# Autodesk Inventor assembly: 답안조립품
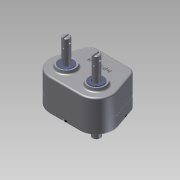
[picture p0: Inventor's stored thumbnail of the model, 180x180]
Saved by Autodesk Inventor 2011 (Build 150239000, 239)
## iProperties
Created: 2014-12
Part Number: 답안조립품
Document SubType Name: Assembly
Designer: SDA
Author: SDA
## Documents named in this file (17)
- C:\Users\SDA\Desktop\441208V1026\답안조립품.iam
- C:\Users\SDA\Desktop\441208V1026\M 5 x 35.ipt
- C:\Users\SDA\Desktop\441208V1026\멈춤링.ipt
- C:\Users\SDA\Desktop\441208V1026\메인기어.ipt
- C:\Users\SDA\Desktop\441208V1026\메인축.ipt
- C:\Users\SDA\Desktop\441208V1026\베어링- 6202.ipt
- C:\Users\SDA\Desktop\441208V1026\베어링- 6203.ipt
- C:\Users\SDA\Desktop\441208V1026\본체.ipt
- C:\Users\SDA\Desktop\441208V1026\서브기어.ipt
- C:\Users\SDA\Desktop\441208V1026\서브축.ipt
- C:\Users\SDA\Desktop\441208V1026\오일시일-D-15.ipt
- C:\Users\SDA\Desktop\441208V1026\오일시일-D-17.ipt
- C:\Users\SDA\Desktop\441208V1026\커버.ipt
- C:\Users\SDA\Desktop\441208V1026\키5x5.ipt
- C:\Users\SDA\Desktop\441208V1026\서브기어_CPY.ipt
- C:\Users\SDA\Desktop\441208V1026\서브축_CPY.ipt
- C:\Users\SDA\Desktop\441208V1026\키5x5_CPY.ipt
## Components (12 placed, 6 different names)
1. KS B 1003 - 미터 M 5 x 35:1
2. KS B 1336 17 x 1:1
3. KS B 2023 6202 - 15 x 35 x 11:1
4. KS B 2023 6203 - 17 x 40 x 12:1
5. KS B 2804 D D - 15 30 7:1
6. KS B 2804 D D - 17 30 8:1
7. KS B 2023 6203 - 17 x 40 x 12:2
8. KS B 2023 6202 - 15 x 35 x 11:2
9. KS B 1336 17 x 1:2
10. KS B 1336 17 x 1:3
11. KS B 1003 - 미터 M 5 x 35:2
12. KS B 1003 - 미터 M 5 x 35:3
